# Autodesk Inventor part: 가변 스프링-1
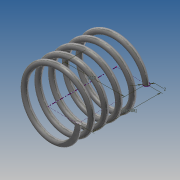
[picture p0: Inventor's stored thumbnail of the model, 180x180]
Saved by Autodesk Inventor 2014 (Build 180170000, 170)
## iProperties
Created: 2016-01
Part Number: 가변 스프링-1
Material: 스테인레스 스틸
Document SubType Name: Modeling
Designer: Administrator
Density: 8.08 g/cm^3
Appearance: 반연마
Mass: 8.62718 g
Surface Area: 21.6509 cm^2
Volume: 1.06772 cm^3
Author: Administrator
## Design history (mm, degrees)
sketch "스케치1"
  geometry: L1 (0, -25.208)-(11, -25.208); L2 (11, -25.208)-(11, 0); L3 (11, 0)-(0, 0); L4 (0, 0)-(0, -25.208); C1 r 1 at (11, 0); 1 further point
  constraints: 8 end point, 2 coincident, 2 parallel, 1 centre point, 1 horizontal, 1 perpendicular
  dimensions: "d0" = 22 diameter of L2.end L4; "d1" = 25.20829 distance of L1.end L2.end (derived); "d2" = 2 diameter of C1
feature "코일1" pitch "d3" = 10; turns "d5" = 5; dims "d4" = 25.20829 (= d1), "d6" = 0, angle "d7" = 90 deg, angle "d8" = 90 deg, "d9" = 0, "d10" = 0
sketch "스케치2"
  geometry: L1 (-10, 0)-(-12, 0) reference; 1 further point
  constraints: 1 horizontal alignment
extrude "돌출1" cut sketch "스케치2" distance "d11" = 10; taper "d12" = 0 deg
node "작업 평면1"
sketch "스케치3"
  geometry: L1 (12, 0)-(10, 0) reference; 1 further point
  constraints: 1 horizontal alignment
extrude "돌출2" cut sketch "스케치3" distance "d14" = 10; taper "d15" = 0 deg
node "솔리드1"
node "절단 모서리 투영1"
node "절단 모서리 투영2"
other parameters: "d13" = 0
